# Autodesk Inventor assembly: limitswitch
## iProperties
Shininess: 0.0
Created: 2002-01
Part Number: limitswitch
Document SubType Name: Assembly
Density: 0.0
Volumn: 0.0
Area: 0.0
PropertySet Name: Model Information
Control State: 0
Master: False
Checked Out: False
Author: Administrator
